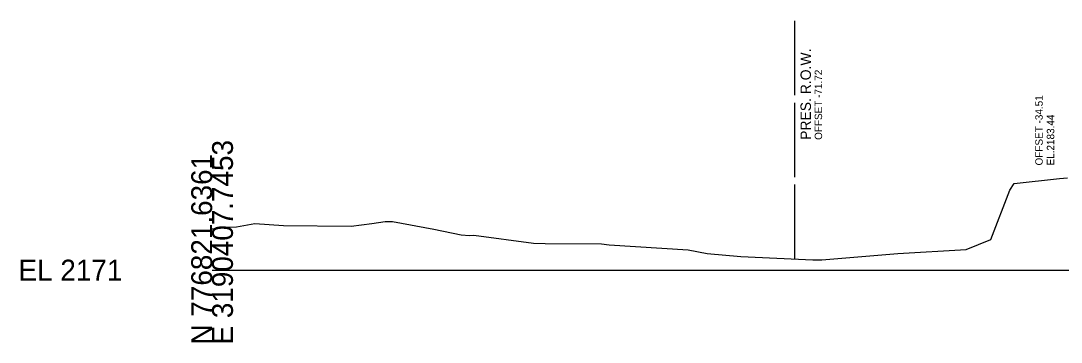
# Model space of a CAD drawing. Extents: x -26 to 303, y -25 to 5046.
# Drawn here: x -25.7 to 114, y 490.3 to 533.5 of the extents above; entities that cross this region are included whole.
import ezdxf

# ---------------------------------------------------------------- set-up
doc = ezdxf.new("R2010")
doc.units = 0
for name, color, linetype in [('DESIGN - SHEET - Light Grid', 7, 'Continuous'), ('DESIGN - TYPICAL - Slope Tie Text', 7, 'Continuous'), ('SURVEY - GROUND - Top of Ground', 7, 'Continuous'), ('SURVEY - PROPERTY - ROW Lines', 7, 'Continuous'), ('SURVEY - PROPERTY - ROW Lines Text', 7, 'Continuous')]:
    doc.layers.add(name, color=color, linetype=linetype)

msp = doc.modelspace()

# ---------------------------------------------------------------- linework, layer by layer
at = {"layer": 'DESIGN - SHEET - Light Grid'}
msp.add_line((0, 500), (150, 500), dxfattribs=at)
at = {"layer": 'SURVEY - GROUND - Top of Ground'}
msp.add_lwpolyline([(0, 505.54), (1.76, 505.76), (3.27, 505.83), (5.73, 506.28), (9.61, 505.97), (18.66, 505.9), (21.44, 506.26), (23.25, 506.52), (24.22, 506.51), (29.76, 505.49), (33.43, 504.75), (34.55, 504.63), (35.16, 504.68), (43.18, 503.63), (44.74, 503.59), (52.3, 503.51), (53.31, 503.41), (63.94, 502.73), (66.5, 502.25), (71.02, 501.84), (80.69, 501.39), (81.9, 501.39), (92.11, 502.21), (101.3, 502.77), (104.6, 504.09), (107.15, 510.72), (107.72, 511.64), (113.81, 512.33), (114.87, 512.42)], dxfattribs=at)
at = {"layer": 'SURVEY - PROPERTY - ROW Lines'}
for p, q in [((78.28, 523.5), (78.28, 533.5)), ((78.28, 512.5), (78.28, 522.5)), ((78.28, 501.5), (78.28, 511.5))]:
    msp.add_line(p, q, dxfattribs=at)

# ---------------------------------------------------------------- texts
at = {"layer": 'DESIGN - SHEET - Light Grid'}
for s, p in [('E 3190407.7453', (2.8, 490)), ('N 776821.6361', (0, 490))]:
    msp.add_text(s, height=2.8, rotation=90, dxfattribs=at).set_placement(p)
msp.add_text('EL 2171', height=2.8, dxfattribs=at).set_placement((-26, 498.6))
at = {"layer": 'DESIGN - TYPICAL - Slope Tie Text'}
for s, p in [('OFFSET -34.51', (111.56, 514.06)), ('EL.2183.44', (113.11, 514.06))]:
    msp.add_text(s, height=1, rotation=90, dxfattribs=at).set_placement(p)
at = {"layer": 'SURVEY - PROPERTY - ROW Lines Text'}
for s, height, p in [('PRES. R.O.W.', 1.4, (80.43, 517.5)), ('OFFSET -71.72', 1, (81.93, 517.5))]:
    msp.add_text(s, height=height, rotation=90, dxfattribs=at).set_placement(p)

doc.saveas('drawing.dxf')
